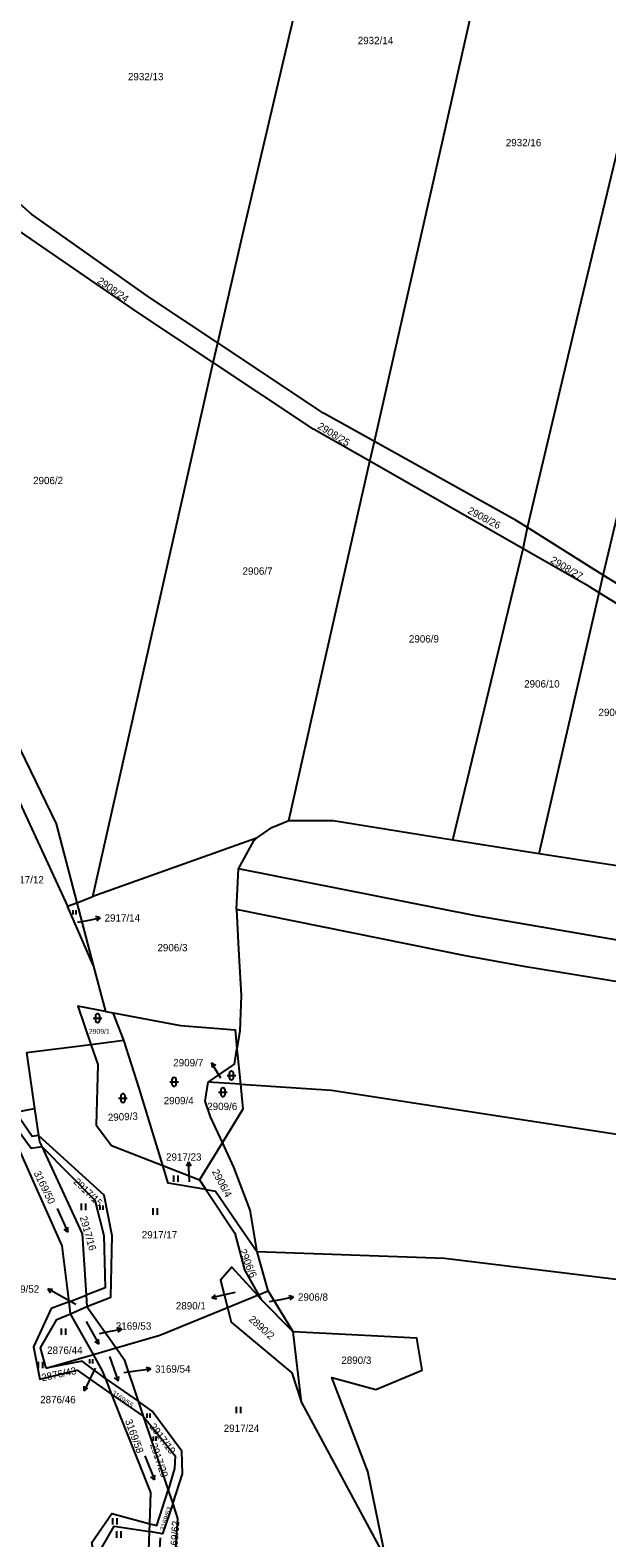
# Model space of a CAD drawing. Extents: x -755528 to -748832, y -1118122 to -1111095.
# Drawn here: x -754079.1 to -753945.5, y -1114445.3 to -1114095.9 of the extents above; entities that cross this region are included whole.
import ezdxf

# ---------------------------------------------------------------- set-up
doc = ezdxf.new("R2010")
doc.units = 0
for name, color, linetype in [('DZ_DO_PUPFL', 7, 'Continuous'), ('DZ_NAD_ZPF', 7, 'Continuous'), ('legenda barvy', 7, 'Continuous'), ('TZ_UMVŽST', 7, 'Continuous')]:
    doc.layers.add(name, color=color, linetype=linetype)

msp = doc.modelspace()

# ---------------------------------------------------------------- linework, layer by layer
at = {"layer": 'DZ_NAD_ZPF'}
for p, q in [((-754036.72, -1114172.95), (-754035.66, -1114168.37)), ((-754064.6, -1114296.7), (-754036.72, -1114172.95)), ((-754000.45, -1114195.8), (-753999.34, -1114191.23)), ((-753964.91, -1114216.11), (-754000.45, -1114195.8)), ((-753964.91, -1114216.11), (-753963.9, -1114211.19)), ((-753946.36, -1114222.18), (-753963.9, -1114211.19)), ((-753981.21, -1114283.54), (-753964.91, -1114216.11)), ((-753947.3, -1114226.28), (-753946.36, -1114222.18)), ((-753929.83, -1114232.54), (-753946.36, -1114222.18)), ((-753961.2, -1114286.73), (-753947.3, -1114226.28)), ((-753930.77, -1114236.47), (-753947.3, -1114226.28)), ((-754101.58, -1114231.65), (-754070.44, -1114298.96)), ((-754026.72, -1114283.18), (-754064.6, -1114296.7)), ((-753981.21, -1114283.54), (-753961.2, -1114286.73)), ((-753961.2, -1114286.73), (-753943.26, -1114289.47)), ((-754031.35, -1114299.67), (-754030.89, -1114290.27)), ((-754070.44, -1114298.96), (-754068.29, -1114298.13)), ((-754064.5, -1114312.64), (-754070.44, -1114298.96)), ((-754068.29, -1114298.13), (-754064.6, -1114296.7)), ((-754068.29, -1114298.13), (-754064.5, -1114312.64)), ((-754064.5, -1114312.64), (-754061.7, -1114323.33)), ((-754061.7, -1114323.33), (-754059.88, -1114323.67)), ((-754057.4, -1114330.01), (-754059.88, -1114323.67)), ((-754065.07, -1114330.98), (-754057.4, -1114330.01)), ((-754079.94, -1114332.85), (-754065.07, -1114330.98)), ((-754079.94, -1114332.85), (-754078.08, -1114345.79)), ((-754031.24, -1114331.99), (-754030.43, -1114340.22)), ((-754030.43, -1114340.22), (-754037.88, -1114339.74)), ((-754082.54, -1114346.65), (-754078.08, -1114345.79)), ((-754078.08, -1114345.79), (-754077.18, -1114352.09)), ((-754034.59, -1114353.67), (-754039.93, -1114362.35)), ((-754048.39, -1114359.07), (-754039.93, -1114362.35)), ((-754039.93, -1114362.35), (-754038.42, -1114364.62)), ((-754023.98, -1114388.06), (-754026.51, -1114379.02)), ((-754070.12, -1114390.62), (-754066.17, -1114389.11)), ((-754066.17, -1114389.11), (-754066.01, -1114391.69)), ((-754033.41, -1114391.93), (-754026.5, -1114389.09)), ((-754025.59, -1114390.09), (-754026.5, -1114389.09)), ((-754026.22, -1114388.98), (-754023.98, -1114388.06)), ((-754026.22, -1114388.98), (-754025.59, -1114390.09)), ((-754018.22, -1114397.62), (-754025.59, -1114390.09)), ((-754018.22, -1114397.62), (-754023.98, -1114388.06)), ((-754069.78, -1114393.4), (-754070.12, -1114390.62)), ((-754069.78, -1114393.4), (-754066.01, -1114391.69)), ((-754064.46, -1114402.84), (-754069.78, -1114393.4)), ((-754066.01, -1114391.69), (-754059.22, -1114401.32)), ((-754016.29, -1114413.97), (-754018.22, -1114397.62)), ((-754075.38, -1114406.01), (-754064.46, -1114402.84)), ((-754064.46, -1114402.84), (-754059.22, -1114401.32)), ((-754060.18, -1114412.12), (-754061.63, -1114408.45)), ((-754061.63, -1114408.45), (-754054.08, -1114413.67)), ((-754060.18, -1114412.12), (-754052.93, -1114417.1)), ((-754054.08, -1114413.67), (-754052.93, -1114417.1)), ((-754016.29, -1114413.97), (-753996.7, -1114450.26)), ((-754052.93, -1114417.1), (-754047.19, -1114434.27)), ((-754047.19, -1114434.27), (-754046.11, -1114437.49)), ((-754051.48, -1114443.88), (-754051.42, -1114442.09)), ((-754051.69, -1114450.44), (-754051.48, -1114443.88))]:
    msp.add_line(p, q, dxfattribs=at)
for points in [[(-753946.36, -1114222.18), (-753926.58, -1114139.03), (-753908.83, -1114065.02), (-753894.06, -1114004.7), (-753890.46, -1113981.25)], [(-753963.9, -1114211.19), (-753951.95, -1114160.75), (-753938.92, -1114106.48), (-753920.5, -1114030.03), (-753910.17, -1113987.88)], [(-753999.34, -1114191.23), (-753983.34, -1114120.28), (-753972.68, -1114072.95), (-753956.63, -1113997.27)], [(-754035.66, -1114168.37), (-754030.23, -1114144.78), (-754016.63, -1114086.74), (-754006.74, -1114042.3), (-754000.1, -1114013.04)], [(-754035.66, -1114168.37), (-754051.47, -1114157.88), (-754078.81, -1114138.51), (-754091.71, -1114127.19)], [(-754036.72, -1114172.95), (-754053.98, -1114161.51), (-754087.81, -1114138.24), (-754093.22, -1114133.86)], [(-753999.34, -1114191.23), (-754011.16, -1114184.64), (-754035.66, -1114168.37)], [(-754000.45, -1114195.8), (-754013.51, -1114188.34), (-754036.72, -1114172.95)], [(-753963.9, -1114211.19), (-753966.54, -1114209.53), (-753999.34, -1114191.23)], [(-754019.17, -1114279.08), (-754011.73, -1114245.73), (-754000.45, -1114195.8)], [(-754108.98, -1114205.82), (-754073.07, -1114279.85), (-754068.29, -1114298.13)], [(-753947.3, -1114226.28), (-753949.66, -1114224.82), (-753964.91, -1114216.11)], [(-754026.72, -1114283.18), (-754023.11, -1114280.67), (-754019.17, -1114279.08)], [(-754019.17, -1114279.08), (-754008.94, -1114279.1), (-753981.21, -1114283.54)], [(-754030.89, -1114290.27), (-754027.34, -1114283.78), (-754026.72, -1114283.18)], [(-753765.07, -1114336.1), (-753821.03, -1114327.8), (-753975.91, -1114301.21), (-754030.89, -1114290.27)], [(-753759.52, -1114346.27), (-753840.42, -1114333.36), (-753889.11, -1114325.26), (-753964.29, -1114313.02), (-753978.31, -1114310.42), (-754031.35, -1114299.67)], [(-754031.35, -1114299.67), (-754030.9, -1114308.93), (-754030.27, -1114319.66), (-754030.58, -1114327.92), (-754031.24, -1114331.99)], [(-754061.7, -1114323.33), (-754068.1, -1114322.08), (-754065.07, -1114330.98)], [(-754059.88, -1114323.67), (-754044.29, -1114326.58), (-754031.67, -1114327.58), (-754031.24, -1114331.99)], [(-754048.39, -1114359.07), (-754053.89, -1114341.11), (-754057.4, -1114330.01)], [(-754065.07, -1114330.98), (-754063.48, -1114335.65), (-754063.84, -1114349.67), (-754060.31, -1114354.44), (-754048.39, -1114359.07)], [(-754037.88, -1114339.74), (-754031.81, -1114335.55), (-754031.24, -1114331.99)], [(-754034.59, -1114353.67), (-754037.35, -1114347.74), (-754038.56, -1114344.12), (-754037.88, -1114339.74)], [(-754030.43, -1114340.22), (-754029.86, -1114345.98), (-754034.59, -1114353.67)], [(-754030.43, -1114340.22), (-754009.35, -1114341.58), (-753941.21, -1114352.06), (-753901.7, -1114358.94), (-753881.46, -1114361.76), (-753833, -1114369.38), (-753779.2, -1114377.65), (-753745.43, -1114382.97)], [(-754077.18, -1114352.09), (-754078.63, -1114352.33), (-754082.54, -1114346.65)], [(-754070.12, -1114390.62), (-754071.69, -1114377.62), (-754081.98, -1114354.52), (-754082.69, -1114349.83)], [(-754082.69, -1114349.83), (-754078.88, -1114355.01), (-754076.45, -1114354.67)], [(-754077.18, -1114352.09), (-754076.97, -1114353.55), (-754076.45, -1114354.67)], [(-754066.01, -1114391.69), (-754060.44, -1114389.54), (-754060.1, -1114375.32), (-754062, -1114365.95), (-754077.18, -1114352.09)], [(-754076.45, -1114354.67), (-754064.11, -1114367.06), (-754062.03, -1114375.23), (-754061.76, -1114387.43), (-754066.17, -1114389.11)], [(-754076.45, -1114354.67), (-754067.04, -1114374.89), (-754066.17, -1114389.11)], [(-754026.51, -1114379.02), (-754028.2, -1114369.38), (-754031.93, -1114359.39), (-754034.59, -1114353.67)], [(-754038.42, -1114364.62), (-754047.14, -1114363.16), (-754048.39, -1114359.07)], [(-754038.42, -1114364.62), (-754036.23, -1114364.99), (-754030.18, -1114373.82), (-754026.51, -1114379.02)], [(-754038.42, -1114364.62), (-754031.69, -1114374.74), (-754029.5, -1114383.25), (-754026.22, -1114388.98)], [(-753746.51, -1114418.17), (-753777.92, -1114412.38), (-753822.95, -1114406.99), (-753843.35, -1114402.99), (-753890.43, -1114395.08), (-753933.9, -1114386.59), (-753983.18, -1114380.59), (-754026.51, -1114379.02)], [(-754026.5, -1114389.09), (-754032.42, -1114382.62), (-754035.05, -1114385.64), (-754033.41, -1114391.93)], [(-754070.12, -1114390.62), (-754074.26, -1114392.2), (-754078.36, -1114401.05), (-754076.87, -1114408.58), (-754068.23, -1114406.51), (-754060.18, -1114412.12)], [(-754075.38, -1114406.01), (-754076.75, -1114401.3), (-754072.94, -1114394.73), (-754069.78, -1114393.4)], [(-754059.22, -1114401.32), (-754049.09, -1114398.37), (-754033.41, -1114391.93)], [(-754033.41, -1114391.93), (-754032.53, -1114395.34), (-754018.5, -1114407.1), (-754016.29, -1114413.97)], [(-753996.7, -1114450.26), (-754000.87, -1114429.93), (-754009.28, -1114408.18), (-753999.04, -1114410.93), (-753988.31, -1114406.51), (-753989.59, -1114399.07), (-754018.22, -1114397.62)], [(-754061.63, -1114408.45), (-754062.42, -1114406.46), (-754064.46, -1114402.84)], [(-754059.22, -1114401.32), (-754057.31, -1114404.02), (-754054.08, -1114413.67)], [(-754061.63, -1114408.45), (-754067.11, -1114404.39), (-754075.38, -1114406.01)], [(-754051.42, -1114442.09), (-754051.18, -1114434.8), (-754060.18, -1114412.12)], [(-754046.11, -1114437.49), (-754043.81, -1114430.51), (-754044, -1114425.22), (-754050.88, -1114415.94), (-754054.08, -1114413.67)], [(-754052.93, -1114417.1), (-754045.53, -1114426.34), (-754045.67, -1114429.28), (-754047.19, -1114434.27)], [(-754051.42, -1114442.09), (-754049.78, -1114442.51), (-754047.19, -1114434.27)], [(-754046.11, -1114437.49), (-754048.45, -1114444.39), (-754051.48, -1114443.88)], [(-754046.11, -1114437.49), (-754044.99, -1114440.83), (-754045.64, -1114449.97)], [(-754051.85, -1114455.37), (-754053.19, -1114453.42), (-754064.3, -1114449.41), (-754064.86, -1114446.4), (-754060.17, -1114439.7), (-754051.42, -1114442.09)], [(-754051.69, -1114450.44), (-754062.57, -1114447.76), (-754059.64, -1114442.63), (-754051.48, -1114443.88)]]:
    msp.add_lwpolyline(points, dxfattribs=at)
at = {"layer": 'legenda barvy'}
for p, q in [((-754068.12, -1114302.65), (-754065.83, -1114302.22)), ((-754065.83, -1114302.22), (-754062.884, -1114301.647)), ((-754062.884, -1114301.647), (-754063.963, -1114301.347)), ((-754062.884, -1114301.647), (-754063.772, -1114302.33)), ((-754035.54, -1114337.78), (-754037.086, -1114335.208)), ((-754037.086, -1114335.208), (-754036.141, -1114335.808)), ((-754037.086, -1114335.208), (-754036.999, -1114336.324)), ((-754034.93, -1114338.8), (-754035.54, -1114337.78)), ((-754042.447, -1114358.163), (-754042.895, -1114359.189)), ((-754042.29, -1114361.16), (-754042.447, -1114358.163)), ((-754042.447, -1114358.163), (-754041.895, -1114359.137)), ((-754042.19, -1114362.85), (-754042.29, -1114361.16)), ((-754072.42, -1114389.1), (-754075.045, -1114387.645)), ((-754075.045, -1114387.645), (-754073.926, -1114387.693)), ((-754075.045, -1114387.645), (-754074.412, -1114388.569)), ((-754068.53, -1114391.22), (-754072.42, -1114389.1)), ((-754037.024, -1114389.685), (-754036.161, -1114388.972)), ((-754034.1, -1114389.01), (-754037.024, -1114389.685)), ((-754037.024, -1114389.685), (-754035.936, -1114389.948)), ((-754031.63, -1114388.44), (-754034.1, -1114389.01)), ((-754023.66, -1114390.59), (-754021.04, -1114390.09)), ((-754021.04, -1114390.09), (-754018.094, -1114389.517)), ((-754018.094, -1114389.517), (-754019.173, -1114389.217)), ((-754018.094, -1114389.517), (-754018.982, -1114390.2)), ((-754060.89, -1114397.55), (-754057.944, -1114396.977)), ((-754057.944, -1114396.977), (-754059.023, -1114396.677)), ((-754057.944, -1114396.977), (-754058.832, -1114397.66)), ((-754063.03, -1114397.98), (-754060.89, -1114397.55)), ((-754064.06, -1114405.98), (-754065.31, -1114408.59)), ((-754057.4, -1114406.98), (-754054.18, -1114406.57)), ((-754054.18, -1114406.57), (-754051.201, -1114406.204)), ((-754051.201, -1114406.204), (-754052.256, -1114405.829)), ((-754051.201, -1114406.204), (-754052.134, -1114406.823)), ((-754066.626, -1114411.287), (-754066.637, -1114410.168)), ((-754065.31, -1114408.59), (-754066.626, -1114411.287)), ((-754066.626, -1114411.287), (-754065.736, -1114410.607))]:
    msp.add_line(p, q, dxfattribs=at)
at = {"layer": 'TZ_UMVŽST'}
for p, q in [((-754069.132, -1114300.88), (-754069.132, -1114299.875)), ((-754068.462, -1114300.88), (-754068.462, -1114299.875)), ((-754064.521, -1114324.881), (-754062.519, -1114324.881)), ((-754064.021, -1114324.381), (-754064.021, -1114325.382)), ((-754063.019, -1114325.382), (-754063.019, -1114324.381)), ((-754033.001, -1114337.681), (-754033.001, -1114338.682)), ((-754031.999, -1114338.682), (-754031.999, -1114337.681)), ((-754046.771, -1114339.661), (-754044.769, -1114339.661)), ((-754046.271, -1114339.161), (-754046.271, -1114340.162)), ((-754045.269, -1114340.162), (-754045.269, -1114339.161)), ((-754033.501, -1114338.181), (-754031.499, -1114338.181)), ((-754058.631, -1114343.421), (-754056.629, -1114343.421)), ((-754058.131, -1114342.921), (-754058.131, -1114343.922)), ((-754057.129, -1114343.922), (-754057.129, -1114342.921)), ((-754035.481, -1114342.061), (-754033.479, -1114342.061)), ((-754034.981, -1114341.561), (-754034.981, -1114342.562)), ((-754033.979, -1114342.562), (-754033.979, -1114341.561)), ((-754045.821, -1114362.85), (-754045.821, -1114361.35)), ((-754044.82, -1114362.85), (-754044.82, -1114361.35)), ((-754072.861, -1114368.979), (-754070.421, -1114374.46)), ((-754067.241, -1114369.36), (-754067.241, -1114367.86)), ((-754066.24, -1114369.36), (-754066.24, -1114367.86)), ((-754062.912, -1114369.29), (-754062.912, -1114368.285)), ((-754062.242, -1114369.29), (-754062.242, -1114368.285)), ((-754050.641, -1114370.45), (-754050.641, -1114368.95)), ((-754049.64, -1114370.45), (-754049.64, -1114368.95)), ((-754070.421, -1114374.46), (-754071.276, -1114373.771)), ((-754070.421, -1114374.46), (-754070.36, -1114373.363)), ((-754071.841, -1114398.31), (-754071.841, -1114396.81)), ((-754070.84, -1114398.31), (-754070.84, -1114396.81)), ((-754066.154, -1114395.175), (-754063.245, -1114400.423)), ((-754063.245, -1114400.423), (-754064.157, -1114399.811)), ((-754063.245, -1114400.423), (-754063.28, -1114399.325)), ((-754065.282, -1114404.95), (-754065.282, -1114403.945)), ((-754064.612, -1114404.95), (-754064.612, -1114403.945)), ((-754060.729, -1114403.332), (-754058.776, -1114409.006)), ((-754077.171, -1114406.01), (-754077.171, -1114404.51)), ((-754076.17, -1114406.01), (-754076.17, -1114404.51)), ((-754058.776, -1114409.006), (-754059.568, -1114408.245)), ((-754058.776, -1114409.006), (-754058.62, -1114407.918)), ((-754052.032, -1114417.53), (-754052.032, -1114416.525)), ((-754051.362, -1114417.53), (-754051.362, -1114416.525)), ((-754031.291, -1114416.48), (-754031.291, -1114414.98)), ((-754030.29, -1114416.48), (-754030.29, -1114414.98)), ((-754050.572, -1114422.87), (-754050.572, -1114421.865)), ((-754049.902, -1114422.87), (-754049.902, -1114421.865)), ((-754052.595, -1114426.348), (-754050.348, -1114431.911)), ((-754050.348, -1114431.911), (-754051.179, -1114431.192)), ((-754050.348, -1114431.911), (-754050.249, -1114430.817)), ((-754060.001, -1114442.26), (-754060.001, -1114440.76)), ((-754059, -1114442.26), (-754059, -1114440.76)), ((-754059.041, -1114445.33), (-754059.041, -1114443.83)), ((-754058.04, -1114445.33), (-754058.04, -1114443.83)), ((-754049.021, -1114445.304), (-754049.232, -1114449.318))]:
    msp.add_line(p, q, dxfattribs=at)
for centre, start, end in [((-754063.52, -1114324.3809), 0, 180), ((-754063.52, -1114325.3809), 180, 359.987886), ((-754032.5, -1114337.6809), 0, 180), ((-754045.77, -1114339.1609), 0, 180), ((-754045.77, -1114340.1609), 180, 359.987886), ((-754034.48, -1114341.5609), 0, 180), ((-754032.5, -1114338.6809), 180, 359.987886), ((-754057.63, -1114342.9209), 0, 180), ((-754057.63, -1114343.9209), 180, 359.987886), ((-754034.48, -1114342.5609), 180, 359.987886)]:
    msp.add_arc(centre, 0.5, start, end, dxfattribs=at)

# ---------------------------------------------------------------- texts
at = {"layer": 'DZ_DO_PUPFL'}
for s, height, p in [('2932/14', 1.7, (-754003.24, -1114099.14)), ('2932/13', 1.7, (-754056.47, -1114107.51)), ('2932/16', 1.7, (-753968.95, -1114122.8)), ('2906/2', 1.7, (-754078.45, -1114201.12)), ('2906/7', 1.7, (-754029.93, -1114222.11)), ('2906/9', 1.7, (-753991.39, -1114237.83)), ('2906/10', 1.7, (-753964.7, -1114248.25)), ('2906/11', 1.7, (-753947.48, -1114254.86)), ('2917/12', 1.7, (-754084.18, -1114293.65)), ('2917/14', 1.7, (-754061.88, -1114302.51)), ('2906/3', 1.7, (-754049.64, -1114309.39)), ('2909/1', 1.14, (-754065.517, -1114328.51)), ('2909/7', 1.7, (-754045.975, -1114336.05)), ('2909/4', 1.7, (-754048.19, -1114344.84)), ('2909/6', 1.7, (-754038.107, -1114346.19)), ('2917/23', 1.7, (-754047.653, -1114357.91)), ('2917/17', 1.7, (-754053.27, -1114375.93)), ('3169/52', 1.7, (-754085.243, -1114388.52)), ('2906/8', 1.7, (-754017.09, -1114390.38)), ('2890/1', 1.7, (-754045.377, -1114392.4)), ('3169/53', 1.7, (-754059.28, -1114397.09)), ('2876/44', 1.7, (-754075.2, -1114402.7)), ('2890/3', 1.7, (-754007.05, -1114405.02)), ('3169/54', 1.7, (-754050.2, -1114407.05)), ('2876/46', 1.7, (-754076.803, -1114414.138)), ('2917/24', 1.7, (-754034.29, -1114420.79))]:
    msp.add_text(s, height=height, dxfattribs=at).set_placement(p)
for s, height, rotation, p in [('2908/24', 1.7, 325, (-754063.767, -1114154.366)), ('2908/25', 1.7, 328, (-754012.72, -1114188.11)), ('2908/26', 1.7, 332, (-753977.969, -1114207.76)), ('2908/27', 1.7, 329, (-753958.777, -1114219.178)), ('2909/3', 1.7, 3, (-754061.085, -1114348.768)), ('3169/50', 1.7, 296, (-754078.353, -1114360.772)), ('2917/15', 1.7, 316, (-754069.23, -1114363.001)), ('2906/4', 1.7, 298, (-754037.07, -1114360.469)), ('2917/16', 1.7, 286, (-754067.667, -1114371.034)), ('2906/6', 1.7, 292, (-754030.708, -1114378.798)), ('2890/2', 1.7, 318, (-754028.638, -1114394.881)), ('2876/43', 1.7, 12, (-754076.323, -1114409.071)), ('3169/55', 1.14, 325, (-754060.372, -1114411.998)), ('3169/58', 1.7, 290, (-754057.178, -1114418.21)), ('2917/19', 1.7, 307, (-754051.588, -1114419.571)), ('2917/20', 1.7, 289, (-754051.393, -1114423.726)), ('3169/63', 1.14, 72, (-754048.02, -1114443.777)), ('3169/62', 1.7, 86, (-754045.132, -1114449.679))]:
    msp.add_text(s, height=height, rotation=rotation, dxfattribs=at).set_placement(p)

doc.saveas('drawing.dxf')
